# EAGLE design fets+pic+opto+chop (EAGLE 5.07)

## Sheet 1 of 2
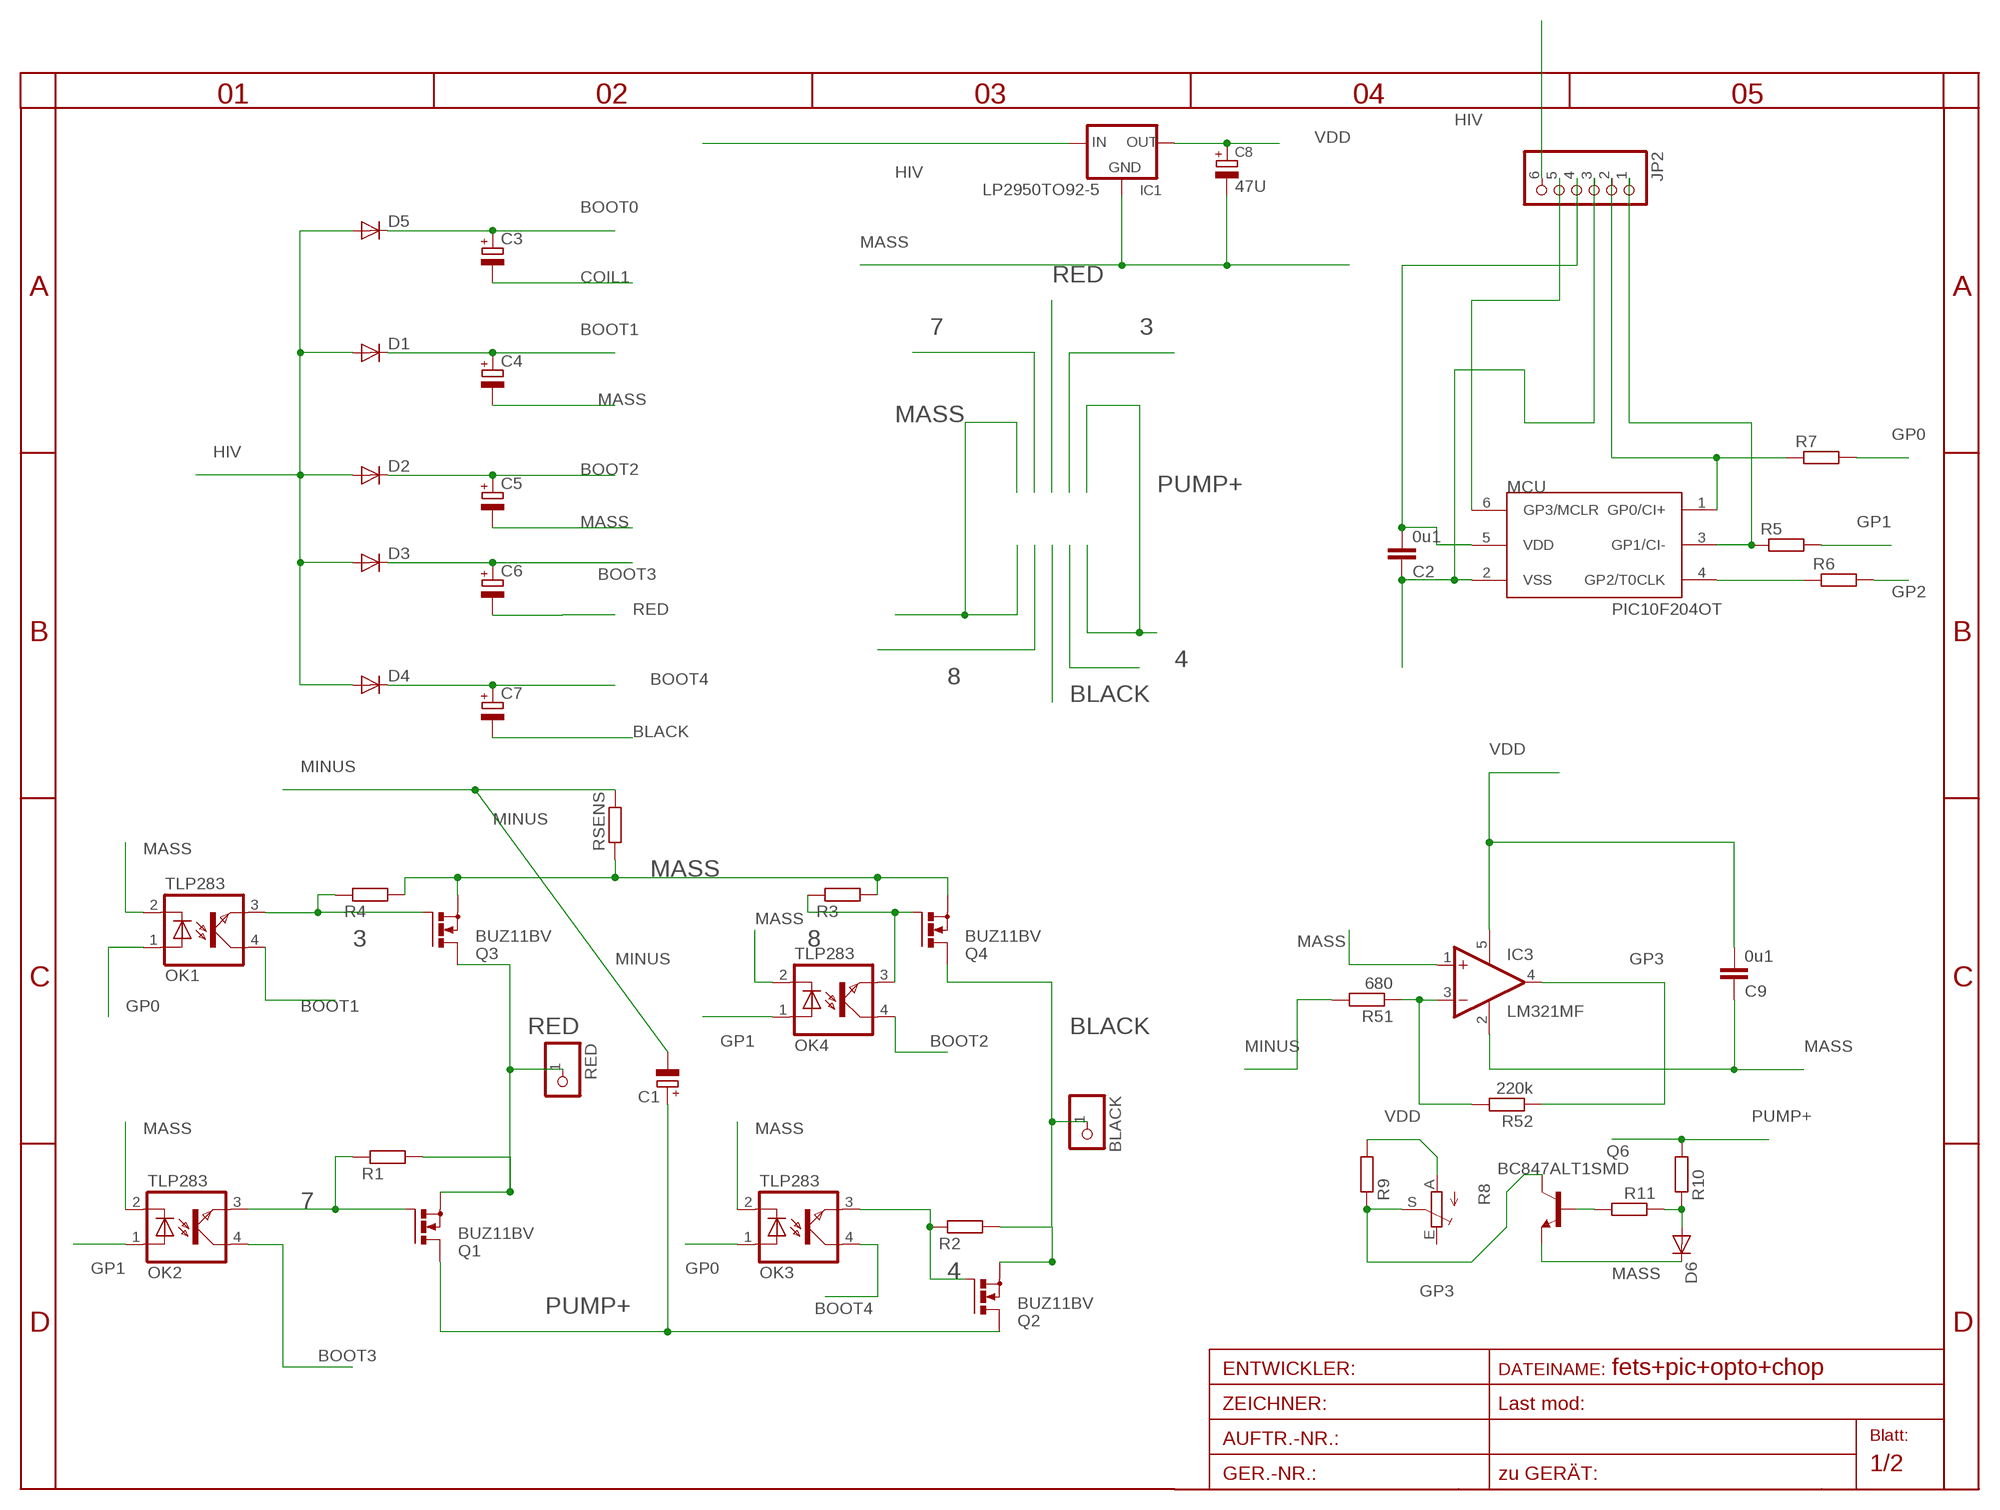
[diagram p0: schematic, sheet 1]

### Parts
BLACK  PINHD-1X14.5MM  [1X4MM5]
C1  CPOL-EUE5-13  [E5-13]
C2  0u1  C-EUC1206  [C1206]
C3  CPOL-EUC  [PANASONIC_C]
C4  CPOL-EUC  [PANASONIC_C]
C5  CPOL-EUC  [PANASONIC_C]
C6  CPOL-EUC  [PANASONIC_C]
C7  CPOL-EUC  [PANASONIC_C]
C8  47U  CPOL-EUE2.5-5  [E2,5-5]
C9  0u1  C-EUC1206  [C1206]
D1  DIODE-SMA-DO214  [SMA-DO214AC]
D2  DIODE-SMA-DO214  [SMA-DO214AC]
D3  DIODE-SMA-DO214  [SMA-DO214AC]
D4  DIODE-SMA-DO214  [SMA-DO214AC]
D5  DIODE-SMA-DO214  [SMA-DO214AC]
D6  DIODE-MINIMELF  [MINIMELF]
IC1  LP2950TO92-5  [T092-5]
IC3  LM321MF  [SOT23-5]
JP2  PINHD-1X6  [1X06BOX]
MCU  PIC10F204OT  [SOT23-6]
OK1  TLP283  [MINI-FLAT-4]
OK2  TLP283  [MINI-FLAT-4]
OK3  TLP283  [MINI-FLAT-4]
OK4  TLP283  [MINI-FLAT-4]
Q1  BUZ11BV  [TO220BV]
Q2  BUZ11BV  [TO220BV]
Q3  BUZ11BV  [TO220BV]
Q4  BUZ11BV  [TO220BV]
Q6  BC847ALT1SMD  [SOT23]
R1  R-EU_R1206  [R1206]
R2  R-EU_R1206  [R1206]
R3  R-EU_R1206  [R1206]
R4  R-EU_R1206  [R1206]
R5  R-EU_R1206  [R1206]
R6  R-EU_R1206  [R1206]
R7  R-EU_R1206  [R1206]
R8  TRIM_EU-S64W  [S64W]
R9  R-EU_R1206  [R1206]
R10  R-EU_R1206  [R1206]
R11  R-EU_R1206  [R1206]
R51  680  R-EU_R0805  [R0805]
R52  220k  R-EU_0207/10  [0207/10]
RED  PINHD-1X14.5MM  [1X4MM5]
RSENS  R-EU_CERAM35  [CERAM35]

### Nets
3: OK1.3(EMIT) Q3.G R4.1
4: OK3.3(EMIT) Q2.G R2.1
7: OK2.3(EMIT) Q1.G R1.1
8: OK4.3(EMIT) Q4.G R3.1
BLACK: BLACK.1 C7.- Q2.S Q4.D R2.2
BOOT0: C3.+ D5.K(C) ; also sheet 2
BOOT1: C4.+ D1.K(C) OK1.4(COL)
BOOT2: C5.+ D2.K(C) OK4.4(COL)
BOOT3: C6.+ D3.K(C) OK2.4(COL)
BOOT4: C7.+ D4.K(C) OK3.4(COL)
COIL1: C3.- ; also sheet 2
GP0: OK1.1(A) OK3.1(A) R7.2
GP0I: JP2.2 MCU.1(GP0/CI+) R7.1
GP1: OK2.1(A) OK4.1(A) R5.2
GP1I: JP2.1 MCU.3(GP1/CI-) R5.1
GP2: R6.2 ; also sheet 2
GP2I: MCU.4(GP2/T0CLK) R6.1
GP3: IC3.4(OUT) JP2.5 MCU.6(GP3/MCLR) Q6.3(C) R8.S R9.1 R52.1
HIV: D1.A D2.A D3.A D4.A D5.A IC1.3(IN) JP2.6 ; also sheet 2
MASS: C2.1 C4.- C5.- C8.- C9.1 D6.C IC1.2(GND) IC3.1(+IN) IC3.2(V-) JP2.3 MCU.2(VSS) OK1.2(C) OK2.2(C) OK3.2(C) OK4.2(C) Q3.S Q4.S Q6.2(E) R3.2 R4.2 RSENS.1 ; also sheet 2
MINUS: C1.- R51.2 RSENS.2 ; also sheet 2
N$4: D6.A R10.1 R11.1
N$5: Q6.1(B) R11.2
N$52: IC3.3(-IN) R51.1 R52.2
PUMP+: C1.+ Q1.D Q2.D R10.2 ; also sheet 2
RED: C6.- Q1.S Q3.D R1.2 RED.1
VDD: C2.2 C8.+ C9.2 IC1.1(OUT) IC3.5(V+) JP2.4 MCU.5(VDD) R8.A R9.2
Unconnected: R8.E

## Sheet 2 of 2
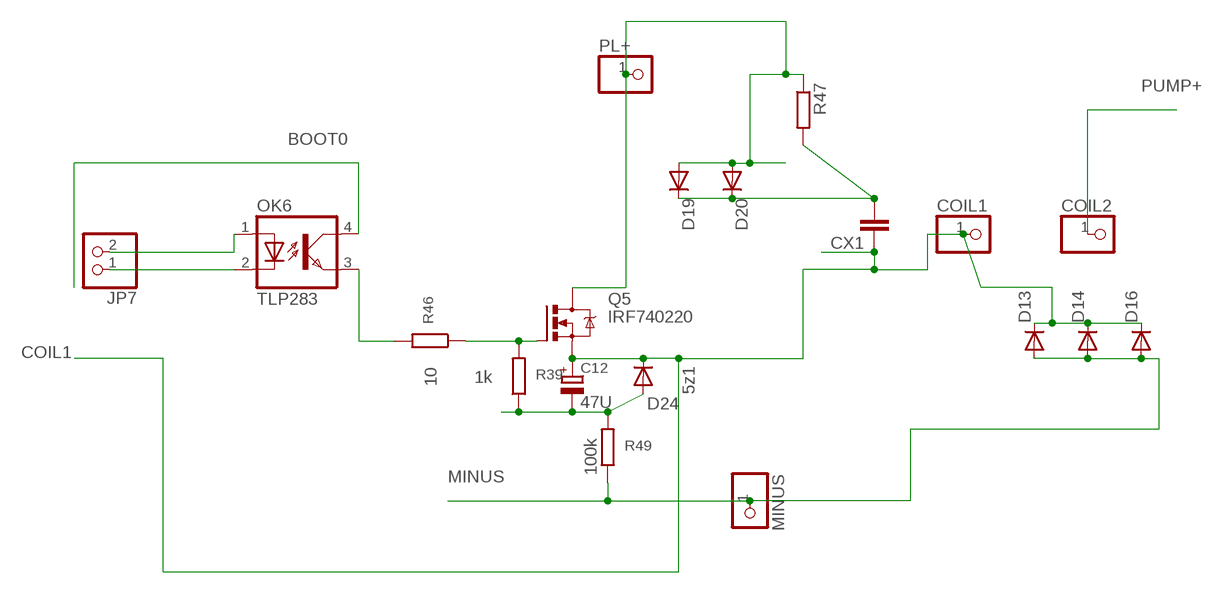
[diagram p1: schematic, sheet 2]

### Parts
C12  47U  CPOL-EUC  [PANASONIC_C]
COIL1  PINHD-1X14.5MM  [1X4MM5]
COIL2  PINHD-1X14.5MM  [1X4MM5]
CX1  CXXC15B6  [XC15B6]
D13  DIODE-SMC  [SMC]
D14  DIODE-SMC  [SMC]
D16  DIODE-SMC  [SMC]
D19  DIODE-SMC  [SMC]
D20  DIODE-SMC  [SMC]
D24  5z1  DIODE-MINIMELF  [MINIMELF]
JP7  PINHD-1X2STR  [1X02]
MINUS  PINHD-1X14.5MM  [1X4MM5]
OK6  TLP283  [MINI-FLAT-4]
PL+  PINHD-1X14.5MM  [1X4MM5]
Q5  IRF740220  [TO220BV]
R39  1k  R-EU_R1206  [R1206]
R46  10  R-EU_R1206  [R1206]
R47  R-EU_0613/15  [P0613/15]
R49  100k  R-EU_0207/15  [0207/15]

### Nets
BATT-: C12.- D24.A R39.1 R49.2
BOOT0: OK6.4(COL) ; also sheet 1
COIL1: C12.+ COIL1.1 CX1.1 D13.C D14.C D16.C D24.C Q5.S ; also sheet 1
GP2: JP7.2 OK6.1(A) ; also sheet 1
HIV: D19.A D20.A PL+.1 Q5.D R47.1 ; also sheet 1
MASS: JP7.1 OK6.2(C) ; also sheet 1
MINUS: D13.A D14.A D16.A MINUS.1 R49.1 ; also sheet 1
N$43: OK6.3(EMIT) R46.2
N$45: Q5.G R39.2 R46.1
PUMP+: COIL2.1 ; also sheet 1
SNUB: CX1.2 D19.C D20.C R47.2

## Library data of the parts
BLACK COIL1 COIL2 MINUS PL+ RED = pinhead:PINHD-1X1: PIN HEADER
C1 C3-C7 = rcl:CPOL-EU: POLARIZED CAPACITOR, European symbol
C2 C9 = rcl:C-EU: CAPACITOR, European symbol
C8 C12 = rcl-2:CPOL-EU: POLARIZED CAPACITOR, European symbol
CX1 = rcl:CX: X CAPACITOR
D1-D6 D13 D14 D16 D19 D20 D24 = diode:DIODE-: DIODE
IC1 = v-reg:LP2950?*: Source: http://cache.national.com/ds/LP/LP2950.pdf
IC3 = linear:LM321?*: Low Power Single Op Amp Source: http://cache.national.com/ds/LM/LM321.pdf
JP2 = pinhead:PINHD-1X6: PIN HEADER
JP7 = pinhead:PINHD-1X2: PIN HEADER
MCU = microchip-3:PIC10F2*: uPC nW 0,25/0,5k Program Flash memory Comparator
OK1-OK4 OK6 = optocoupler:TLP283: TOSHIBA PHOTOCOUPLER GaAs IRED & PHOTO-TRANSISTOR Source: http://www.semicon.toshiba.co.jp/td/en/Opto/Photocoupler/en_20050928_TLP283_datasheet.pdf
Q1-Q4 = transistor-power:BUZ11: N-CHANNEL MOS FET
Q5 = transistor-power:IRF740: N-CHANNEL MOS FET
Q6 = transistor-npn:BC847*: NPN Transistor
R1-R7 R9-R11 R47 R51 R52 RSENS = rcl:R-EU_: RESISTOR, European symbol
R8 = pot:TRIM_EU-: POTENTIOMETER
R39 R46 R49 = rcl-2:R-EU_: RESISTOR, European symbol

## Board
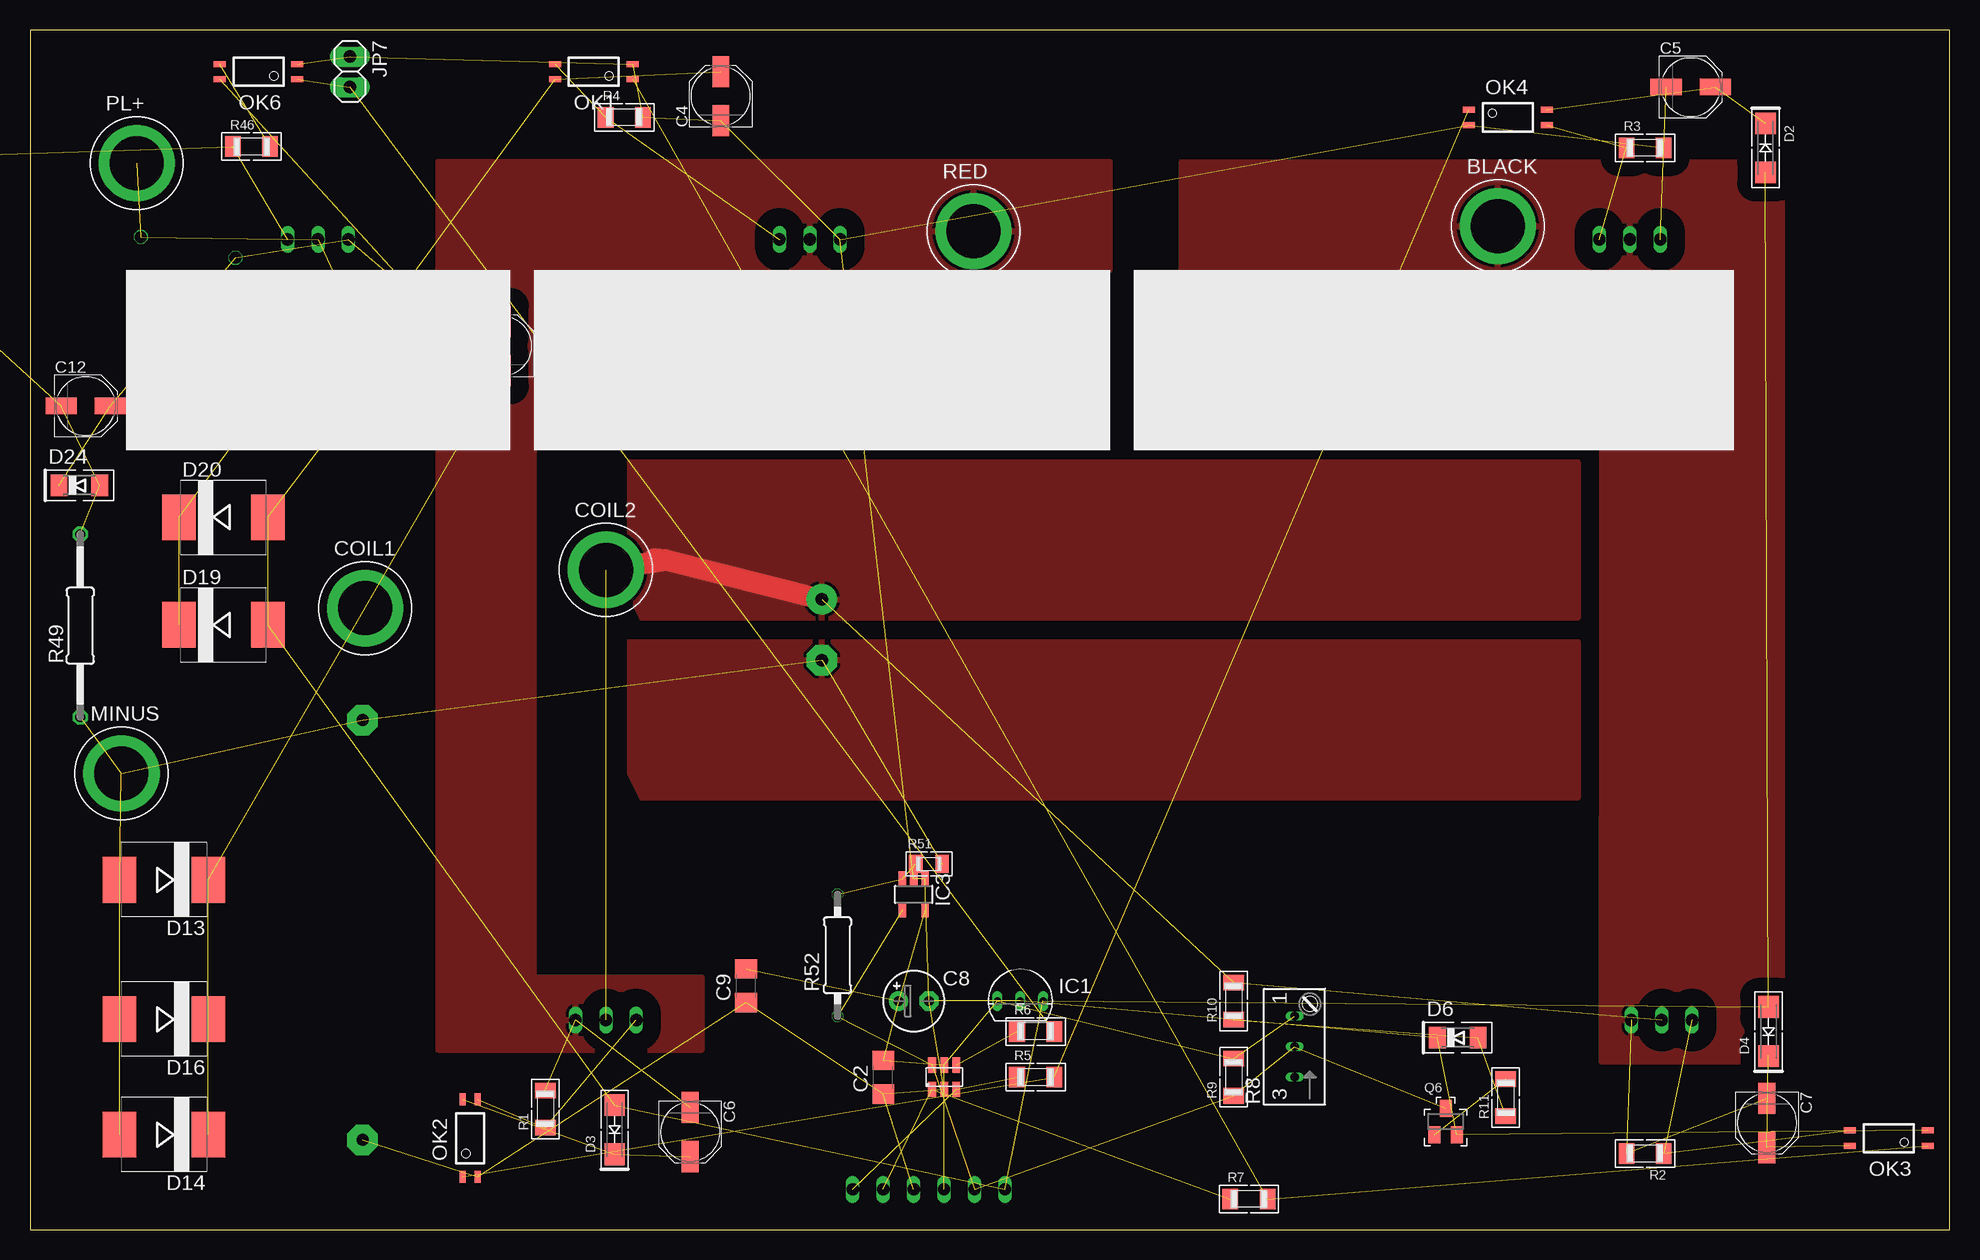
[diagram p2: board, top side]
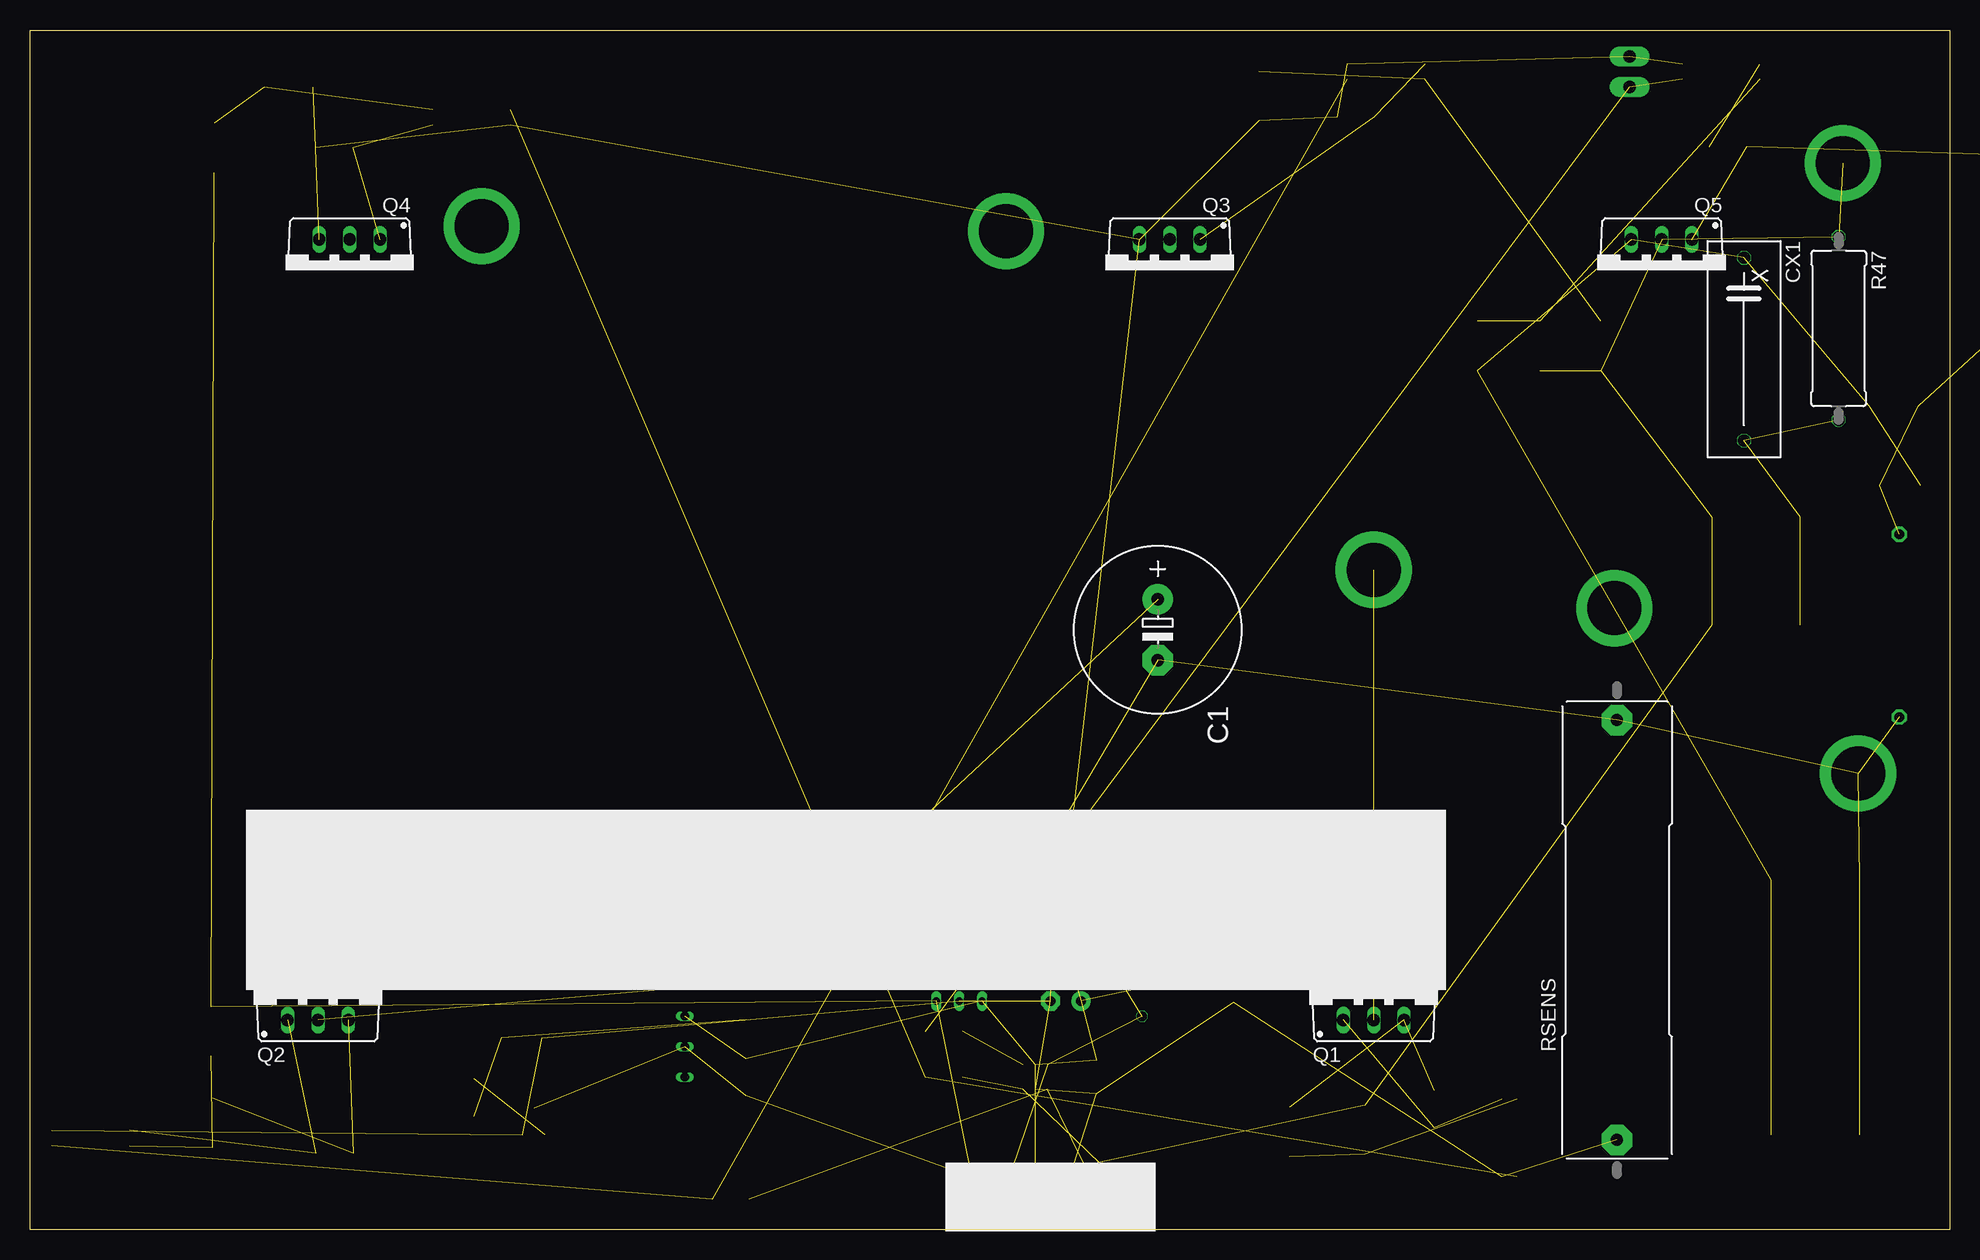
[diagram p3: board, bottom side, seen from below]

Size 160 x 100 mm. Coordinates in mm from the lower left corner, seen from the top.
Outline: 0,0 160,0 160,100 0,100 0,0
Copper layers (1*16): Top 0.035mm / dielectric 1.5mm / Bottom 0.035mm
Design rules "default": minimum track width 10mil, minimum drill 20mil, track to track 8mil, track to pad 8mil, pad to pad 8mil, via to via 8mil, smd to smd 8mil, copper to edge 40mil, drill to drill 8mil, minimum pad ring 1mil, minimum via ring 8mil, stop-mask expansion 4mil, vias tented up to drill 0mil, thermal gap 10mil

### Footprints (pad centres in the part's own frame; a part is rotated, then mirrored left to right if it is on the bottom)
1X4MM5 = drill 4.5 pad 6.35 round: 1 0,0
E5-13 = drill 1.016 pad 2.54 round: + -2.54,0 | drill 1.016 pad 2.54 octagon: - 2.54,0
C1206 = smd 1.6 x 1.8: 1 -1.4,0; 2 1.4,0
PANASONIC_C = smd 2.6 x 1.4: + 2.05,0; - -2.05,0
E2,5-5 = drill 0.813 pad 1.6 round: + -1.27,0 | drill 0.813 pad 1.6 octagon: - 1.27,0
XC15B6 = drill 1.016 octagon: 1 -7.62,0; 2 7.62,0
SMA-DO214AC = smd 1.8 x 1.7: A 2.05,-0.127; K -2.05,-0.127
MINIMELF = smd 1.4 x 1.8: A 1.7,0; C -1.7,0
SMC = smd 2.8 x 3.8: A 3.7,0; C -3.7,0
T092-5 = drill 0.6 pad 0.813 long: 1 -1.905,0; 2 0,0; 3 1.905,0
SOT23-5 = smd 0.6 x 1.2: 1 -0.95,-1.306; 2 0,-1.306; 3 0.95,-1.306; 4 0.95,1.306; 5 -0.95,1.306
1X06BOX = drill 1.016 long: 1 -6.35,0; 2 -3.81,0; 3 -1.27,0; 4 1.27,0; 5 3.81,0; 6 6.35,0
1X02 = drill 1.016 pad 1.676 long: 1 -1.27,0; 2 1.27,0
SOT23-6 = smd 0.635 x 1.27: 1 -1.016,-1.016; 2 0,-1.016; 3 1.016,-1.016; 4 1.016,1.016; 5 0,1.016; 6 -1.016,1.016
MINI-FLAT-4 = smd 1 x 0.5: 1 -3.24,0.635; 2 -3.24,-0.635; 3 3.24,-0.635; 4 3.24,0.635
TO220BV = drill 1.016 long: D 0,-2.54; G -2.54,-2.54; S 2.54,-2.54
SOT23 = smd 1 x 1.4: 1 -0.95,-1.1; 2 0.95,-1.1; 3 0,1.1
R1206 = smd 1.3 x 1.7: 1 -1.55,0; 2 1.55,0
S64W = drill 0.7 long: A 2.54,1.27; E -2.54,1.27; S 0,1.27
P0613/15 = drill 1.016 octagon: 1 -7.62,0; 2 7.62,0
0207/15 = drill 0.8 pad 1.27 octagon: 1 -7.62,0; 2 7.62,0
R0805 = smd 1.1 x 1.5: 1 -1.1,0; 2 1.1,0
0207/10 = drill 0.813 octagon: 1 -5.08,0; 2 5.08,0
CERAM35 = drill 1 pad 2.54 octagon: 1 -17.5,0; 2 17.5,0

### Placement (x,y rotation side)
BLACK  122.35,83.64 0 top
C1  66,50 270 bottom
C2  71.12,12.7 90 top
C3  39.37,73.66 90 top
C4  57.58,94.48 90 top
C5  138.43,95.25 0 top
C6  55.02,8.13 270 top
C7  144.78,8.89 270 top
C8  73.66,19.05 0 top
C9  59.69,20.32 90 top
C12  4.65,68.66 0 top
COIL1  27.94,51.8 0 top
COIL2  48,55 0 top
CX1  17.13,73.39 270 bottom
D1  29.21,73.66 270 top
D2  144.78,90.17 270 top
D3  48.6,8.32 90 top
D4  144.78,16.51 90 top
D5  34.29,73.66 270 top
D6  119,16 0 top
D13  11.16,29.15 180 top
D14  11.16,7.91 180 top
D16  11.16,17.53 180 top
D19  16.12,50.41 0 top
D20  16.12,59.38 0 top
D24  4.11,62.04 0 top
IC1  82.55,19.05 0 top
IC3  73.66,27.94 180 top
JP2  74.93,3.35 180 bottom
JP7  26.67,96.52 270 top
MCU  76.2,12.7 0 top
MINUS  7.62,38.02 0 top
OK1  46.99,96.52 180 top
OK2  36.68,7.62 90 top
OK3  154.94,7.62 180 top
OK4  123.19,92.71 0 top
OK6  19.05,96.52 180 top
PL+  8.89,88.9 0 top
Q1  48,20 0 bottom
Q2  136,20 0 bottom
Q3  65,80 180 bottom
Q4  133.35,80 180 bottom
Q5  24,80 180 bottom
Q6  118,9 0 top
R1  42.95,10.05 90 top
R2  134.62,6.35 180 top
R3  134.62,90.17 0 top
R4  49.53,92.71 0 top
R5  83.82,12.7 0 top
R6  83.82,16.51 0 top
R7  101.6,2.54 0 top
R8  106.68,15.24 90 top
R9  100.33,12.7 90 top
R10  100.33,19.05 90 top
R11  123,11 90 top
R39  not placed on the board
R46  18.46,90.28 0 top
R47  9.24,75.12 270 bottom
R49  4.19,50.34 90 top
R51  74.93,30.48 0 top
R52  67.31,22.86 90 top
RED  78.65,83.23 0 top
RSENS  27.71,24.96 90 bottom

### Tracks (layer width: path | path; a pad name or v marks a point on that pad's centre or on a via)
3  (2 unrouted)
4  (2 unrouted)
7  (2 unrouted)
8  (2 unrouted)
BATT-  (3 unrouted)
BLACK  (2 unrouted)
  pour Top (isolate 1.5, rank 2): 96,89 146,89 146,14 131,14 131,79 96,79
BOOT0  (2 unrouted)
BOOT1  (2 unrouted)
BOOT2  (2 unrouted)
BOOT3  (2 unrouted)
BOOT4  (2 unrouted)
COIL1  (8 unrouted)
GP0  (2 unrouted)
GP0I  (2 unrouted)
GP1  (2 unrouted)
GP1I  (2 unrouted)
GP2  (2 unrouted)
GP2I  (1 unrouted)
GP3  (6 unrouted)
HIV  (11 unrouted)
MASS  (22 unrouted)
MINUS  (7 unrouted)
  pour Top (isolate 1.5): 50,49 129,49 129,36 51,36 50,38
N$4  (2 unrouted)
N$5  (1 unrouted)
N$43  (1 unrouted)
N$45  (2 unrouted)
N$52  (2 unrouted)
PUMP+  (3 unrouted)
  Top 1.778: 52.98,55.8 52.07,55.88 | 52.98,55.8 C1.+ | COIL2.1 52.98,55.8
  pour Top (isolate 1.5): 50,64 129,64 129,51 51,51 50,53
RED  (2 unrouted)
  pour Top (isolate 1.5, rank 2): 90,80 90,89 34,89 34,15 56,15 56,21 42,21 42,80
SNUB  (3 unrouted)
VDD  (8 unrouted)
